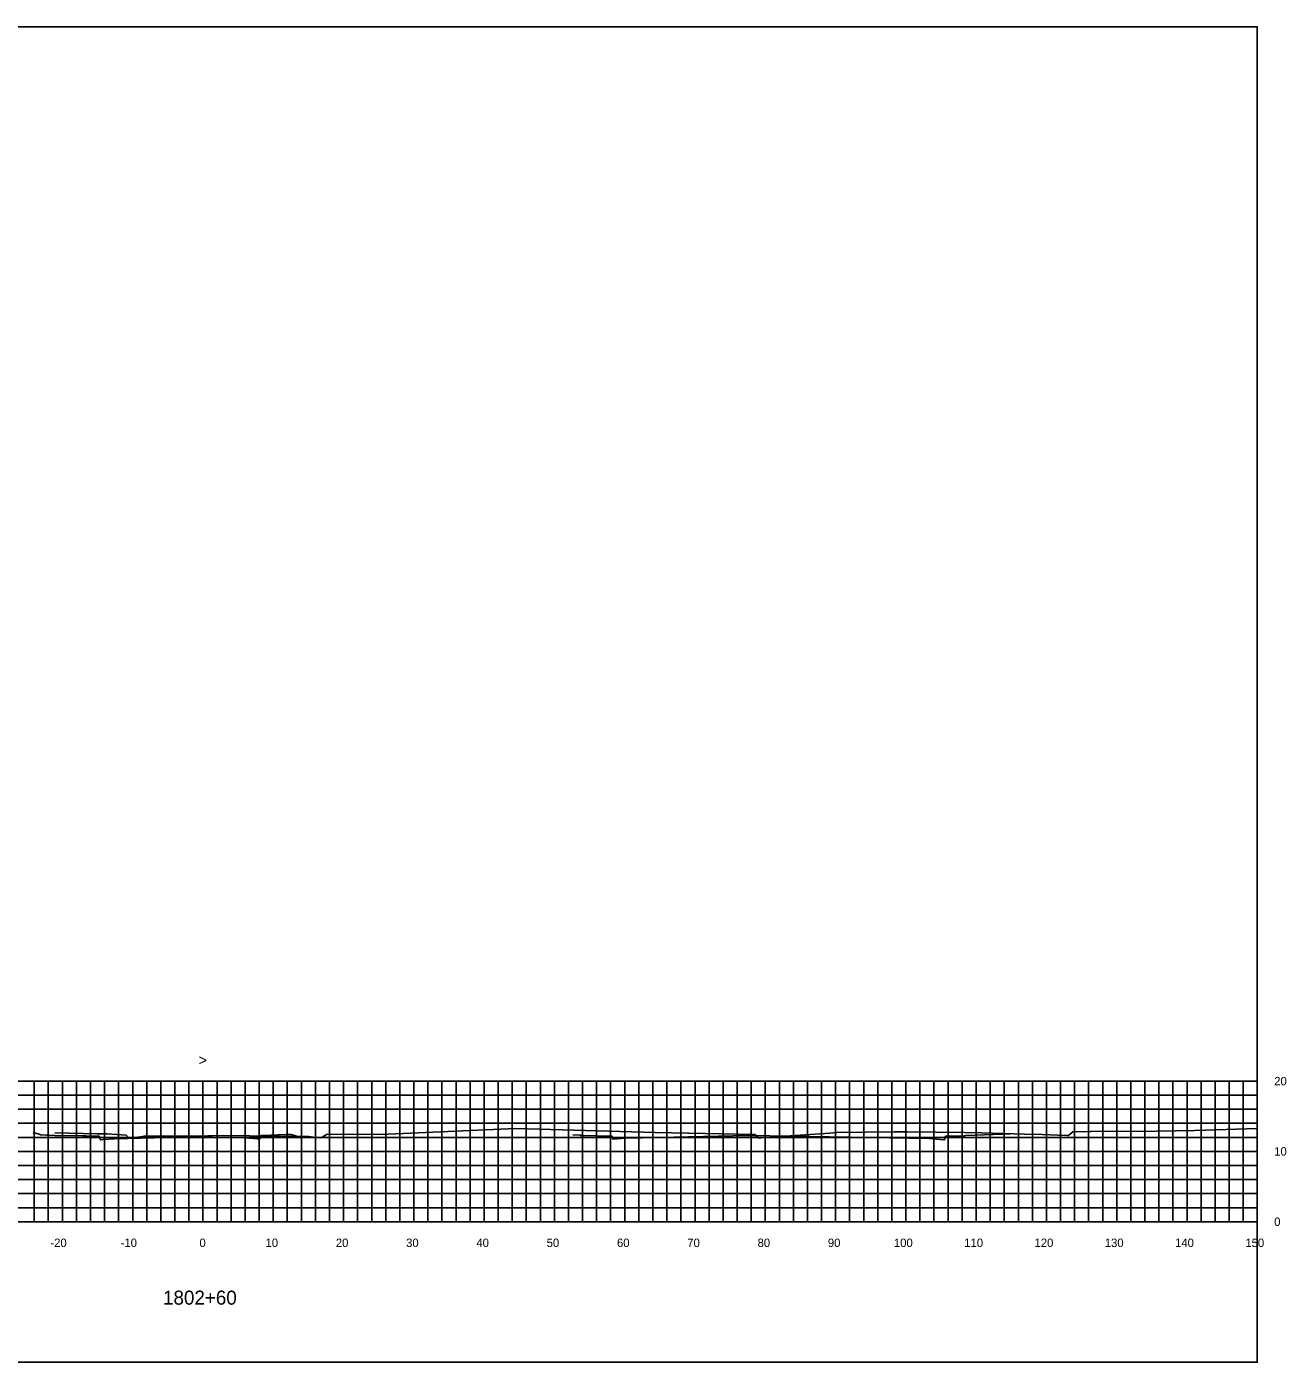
# Model space of a CAD drawing. Extents: x 1797759 to 1802785, y 249826 to 250371.
# Drawn here: x 1799971.1 to 1800150.3, y 249825.9 to 250015.9 of the extents above; entities that cross this region are included whole.
import ezdxf

# ---------------------------------------------------------------- set-up
doc = ezdxf.new("R2010")
doc.units = 0
for name, color, linetype in [('AXIS', 7, 'Continuous'), ('great seal', 7, 'Continuous'), ('Level 1', 7, 'Continuous'), ('Level 10', 7, 'Continuous'), ('Level 15', 7, 'Continuous'), ('Level 30', 7, 'Continuous'), ('Level 45', 7, 'Continuous'), ('Level 7', 7, 'Continuous')]:
    doc.layers.add(name, color=color, linetype=linetype)

msp = doc.modelspace()

# ---------------------------------------------------------------- linework, layer by layer
at = {"layer": 'AXIS'}
msp.add_lwpolyline([(1799846.22, 249825.85), (1800146.22, 249825.85), (1800146.22, 250015.85), (1799846.22, 250015.85)], close=True, dxfattribs=at)
msp.add_lwpolyline([(1800048.86, 249858.21), (1800049.85, 249858.18), (1800049.97, 249858.18), (1800050.01, 249858.07), (1800050.49, 249858.11), (1800053.95, 249858), (1800054.39, 249858), (1800054.54, 249857.6), (1800056.32, 249857.74), (1800061.11, 249857.85), (1800073.69, 249858.14), (1800076.85, 249858.08), (1800099.54, 249857.67), (1800101.61, 249857.51), (1800101.7, 249857.51), (1800101.71, 249857.53), (1800101.88, 249858.01), (1800101.9, 249858.01), (1800102.42, 249858.01), (1800104.5, 249858.09), (1800104.57, 249858.09), (1800104.74, 249858.1), (1800109.96, 249858.31), (1800111.02, 249858.35), (1800111.03, 249858.35), (1800111.06, 249858.36), (1800111.11, 249858.37)], dxfattribs=at)
at = {"layer": 'great seal'}
msp.add_lwpolyline([(1799975.14, 249858.51), (1799981.18, 249858.36), (1799982.19, 249858.37), (1799982.59, 249858.35), (1799985.31, 249858.16), (1799985.59, 249857.86), (1799985.72, 249857.74), (1799987.29, 249857.95), (1799987.87, 249858), (1799996.89, 249858.09), (1799999.09, 249858.13), (1800002.85, 249858.09), (1800011.3, 249857.97), (1800012.26, 249857.85), (1800013, 249857.78), (1800013.51, 249858.08), (1800013.8, 249858.27), (1800022.56, 249858.31), (1800033.19, 249858.78), (1800040.72, 249859.11), (1800060.56, 249858.56), (1800074.77, 249858.25), (1800075.1, 249857.9), (1800075.23, 249857.75), (1800075.7, 249857.8), (1800076.96, 249857.9), (1800085.42, 249858.45), (1800086.42, 249858.52), (1800094.57, 249858.63), (1800096.42, 249858.65), (1800104.54, 249858.55), (1800106.96, 249858.51), (1800113.08, 249858.32), (1800115.62, 249858.25), (1800117.82, 249858.18), (1800119.23, 249858.12), (1800119.36, 249858.11), (1800119.39, 249858.15), (1800119.96, 249858.64), (1800122.48, 249858.67), (1800131.83, 249858.71), (1800137.35, 249858.83), (1800146.22, 249859.1)], dxfattribs=at)
at = {"layer": 'Level 1'}
msp.add_lwpolyline([(1799972.07, 249858.56), (1799972.76, 249858.33), (1799973.15, 249858.2), (1799973.95, 249858.16), (1799974.15, 249858.16), (1799975.14, 249858.14), (1799979.14, 249858.08), (1799979.54, 249858.07), (1799981.14, 249858), (1799981.4, 249858), (1799981.47, 249858), (1799981.5, 249857.9), (1799981.63, 249857.5), (1799982.03, 249857.53), (1799983.63, 249857.66), (1799993.14, 249857.87), (1799995.61, 249857.93), (1799999.52, 249857.84), (1800002.31, 249857.78), (1800003.92, 249857.65), (1800004.3, 249857.62), (1800004.44, 249858.02), (1800004.47, 249858.12), (1800004.74, 249858.12), (1800004.8, 249858.12), (1800008.02, 249858.25), (1800008.79, 249858.28), (1800010, 249857.88), (1800010.3, 249857.98)], dxfattribs=at)
at = {"layer": 'Level 15'}
for p, q in [((1799846.22, 249865.85), (1800146.22, 249865.85)), ((1799972.22, 249845.85), (1799972.22, 249865.85)), ((1799974.22, 249845.85), (1799974.22, 249865.85)), ((1799976.22, 249845.85), (1799976.22, 249865.85)), ((1799978.22, 249845.85), (1799978.22, 249865.85)), ((1799980.22, 249845.85), (1799980.22, 249865.85)), ((1799982.22, 249845.85), (1799982.22, 249865.85)), ((1799984.22, 249845.85), (1799984.22, 249865.85)), ((1799986.22, 249845.85), (1799986.22, 249865.85)), ((1799988.22, 249845.85), (1799988.22, 249865.85)), ((1799990.22, 249845.85), (1799990.22, 249865.85)), ((1799992.22, 249845.85), (1799992.22, 249865.85)), ((1799994.22, 249845.85), (1799994.22, 249865.85)), ((1799996.22, 249845.85), (1799996.22, 249865.85)), ((1799998.22, 249845.85), (1799998.22, 249865.85)), ((1800000.22, 249845.85), (1800000.22, 249865.85)), ((1800002.22, 249845.85), (1800002.22, 249865.85)), ((1800004.22, 249845.85), (1800004.22, 249865.85)), ((1800006.22, 249845.85), (1800006.22, 249865.85)), ((1800008.22, 249845.85), (1800008.22, 249865.85)), ((1800010.22, 249845.85), (1800010.22, 249865.85)), ((1800012.22, 249845.85), (1800012.22, 249865.85)), ((1800014.22, 249845.85), (1800014.22, 249865.85)), ((1800016.22, 249845.85), (1800016.22, 249865.85)), ((1800018.22, 249845.85), (1800018.22, 249865.85)), ((1800020.22, 249845.85), (1800020.22, 249865.85)), ((1800022.22, 249845.85), (1800022.22, 249865.85)), ((1800024.22, 249845.85), (1800024.22, 249865.85)), ((1800026.22, 249845.85), (1800026.22, 249865.85)), ((1800028.22, 249845.85), (1800028.22, 249865.85)), ((1800030.22, 249845.85), (1800030.22, 249865.85)), ((1800032.22, 249845.85), (1800032.22, 249865.85)), ((1800034.22, 249845.85), (1800034.22, 249865.85)), ((1800036.22, 249845.85), (1800036.22, 249865.85)), ((1800038.22, 249845.85), (1800038.22, 249865.85)), ((1800040.22, 249845.85), (1800040.22, 249865.85)), ((1800042.22, 249845.85), (1800042.22, 249865.85)), ((1800044.22, 249845.85), (1800044.22, 249865.85)), ((1800046.22, 249845.85), (1800046.22, 249865.85)), ((1800048.22, 249845.85), (1800048.22, 249865.85)), ((1800050.22, 249845.85), (1800050.22, 249865.85)), ((1800052.22, 249845.85), (1800052.22, 249865.85)), ((1800054.22, 249845.85), (1800054.22, 249865.85)), ((1800056.22, 249845.85), (1800056.22, 249865.85)), ((1800058.22, 249845.85), (1800058.22, 249865.85)), ((1800060.22, 249845.85), (1800060.22, 249865.85)), ((1800062.22, 249845.85), (1800062.22, 249865.85)), ((1800064.22, 249845.85), (1800064.22, 249865.85)), ((1800066.22, 249845.85), (1800066.22, 249865.85)), ((1800068.22, 249845.85), (1800068.22, 249865.85)), ((1800070.22, 249845.85), (1800070.22, 249865.85)), ((1800072.22, 249845.85), (1800072.22, 249865.85)), ((1800074.22, 249845.85), (1800074.22, 249865.85)), ((1800076.22, 249845.85), (1800076.22, 249865.85)), ((1800078.22, 249845.85), (1800078.22, 249865.85)), ((1800080.22, 249845.85), (1800080.22, 249865.85)), ((1800082.22, 249845.85), (1800082.22, 249865.85)), ((1800084.22, 249845.85), (1800084.22, 249865.85)), ((1800086.22, 249845.85), (1800086.22, 249865.85)), ((1800088.22, 249845.85), (1800088.22, 249865.85)), ((1800090.22, 249845.85), (1800090.22, 249865.85)), ((1800092.22, 249845.85), (1800092.22, 249865.85)), ((1800094.22, 249845.85), (1800094.22, 249865.85)), ((1800096.22, 249845.85), (1800096.22, 249865.85)), ((1800098.22, 249845.85), (1800098.22, 249865.85)), ((1800100.22, 249845.85), (1800100.22, 249865.85)), ((1800102.22, 249845.85), (1800102.22, 249865.85)), ((1800104.22, 249845.85), (1800104.22, 249865.85)), ((1800106.22, 249845.85), (1800106.22, 249865.85)), ((1800108.22, 249845.85), (1800108.22, 249865.85)), ((1800110.22, 249845.85), (1800110.22, 249865.85)), ((1800112.22, 249845.85), (1800112.22, 249865.85)), ((1800114.22, 249845.85), (1800114.22, 249865.85)), ((1800116.22, 249845.85), (1800116.22, 249865.85)), ((1800118.22, 249845.85), (1800118.22, 249865.85)), ((1800120.22, 249845.85), (1800120.22, 249865.85)), ((1800122.22, 249845.85), (1800122.22, 249865.85)), ((1800124.22, 249845.85), (1800124.22, 249865.85)), ((1800126.22, 249845.85), (1800126.22, 249865.85)), ((1800128.22, 249845.85), (1800128.22, 249865.85)), ((1800130.22, 249845.85), (1800130.22, 249865.85)), ((1800132.22, 249845.85), (1800132.22, 249865.85)), ((1800134.22, 249845.85), (1800134.22, 249865.85)), ((1800136.22, 249845.85), (1800136.22, 249865.85)), ((1800138.22, 249845.85), (1800138.22, 249865.85)), ((1800140.22, 249845.85), (1800140.22, 249865.85)), ((1800142.22, 249845.85), (1800142.22, 249865.85)), ((1800144.22, 249845.85), (1800144.22, 249865.85)), ((1800146.22, 249845.85), (1800146.22, 249865.85)), ((1799846.22, 249863.85), (1800146.22, 249863.85)), ((1799846.22, 249861.85), (1800146.22, 249861.85)), ((1799846.22, 249859.85), (1800146.22, 249859.85)), ((1799846.22, 249857.85), (1800146.22, 249857.85)), ((1799846.22, 249855.85), (1800146.22, 249855.85)), ((1799846.22, 249853.85), (1800146.22, 249853.85)), ((1799846.22, 249851.85), (1800146.22, 249851.85)), ((1799846.22, 249849.85), (1800146.22, 249849.85)), ((1799846.22, 249847.85), (1800146.22, 249847.85)), ((1799846.22, 249845.85), (1800146.22, 249845.85))]:
    msp.add_line(p, q, dxfattribs=at)
at = {"layer": 'Level 30'}
for p, q in [((1800146.22, 249845.85), (1800146.22, 249865.85)), ((1800146.28, 249865.85), (1800146.22, 249865.85)), ((1800146.28, 249855.85), (1800146.22, 249855.85)), ((1799846.22, 249845.85), (1800146.22, 249845.85)), ((1799976.22, 249845.79), (1799976.22, 249845.85)), ((1799986.22, 249845.79), (1799986.22, 249845.85)), ((1799996.22, 249845.79), (1799996.22, 249845.85)), ((1800006.22, 249845.79), (1800006.22, 249845.85)), ((1800016.22, 249845.79), (1800016.22, 249845.85)), ((1800026.22, 249845.79), (1800026.22, 249845.85)), ((1800036.22, 249845.79), (1800036.22, 249845.85)), ((1800046.22, 249845.79), (1800046.22, 249845.85)), ((1800056.22, 249845.79), (1800056.22, 249845.85)), ((1800066.22, 249845.79), (1800066.22, 249845.85)), ((1800076.22, 249845.79), (1800076.22, 249845.85)), ((1800086.22, 249845.79), (1800086.22, 249845.85)), ((1800096.22, 249845.79), (1800096.22, 249845.85)), ((1800106.22, 249845.79), (1800106.22, 249845.85)), ((1800116.22, 249845.79), (1800116.22, 249845.85)), ((1800126.22, 249845.79), (1800126.22, 249845.85)), ((1800136.22, 249845.79), (1800136.22, 249845.85)), ((1800146.22, 249845.79), (1800146.22, 249845.85)), ((1800146.28, 249845.85), (1800146.22, 249845.85))]:
    msp.add_line(p, q, dxfattribs=at)

# ---------------------------------------------------------------- texts
at = {"layer": 'Level 10'}
msp.add_text('1802+60', height=2, dxfattribs=at).set_placement((1799990.54, 249834.05))
at = {"layer": 'Level 30'}
msp.add_text('>', height=1.5, dxfattribs=at).set_placement((1799995.61, 249868.1))
at = {"layer": 'Level 45'}
for s, p in [('-20', (1799974.51, 249842.25)), ('-10', (1799984.51, 249842.25)), ('0', (1799995.72, 249842.25)), ('10', (1800005.12, 249842.25)), ('20', (1800015.12, 249842.25)), ('30', (1800025.12, 249842.25)), ('40', (1800035.12, 249842.25)), ('50', (1800045.12, 249842.25)), ('60', (1800055.12, 249842.25)), ('70', (1800065.12, 249842.25)), ('80', (1800075.12, 249842.25)), ('90', (1800085.12, 249842.25)), ('100', (1800094.52, 249842.25)), ('110', (1800104.52, 249842.25)), ('120', (1800114.52, 249842.25)), ('130', (1800124.52, 249842.25)), ('140', (1800134.52, 249842.25)), ('150', (1800144.52, 249842.25))]:
    msp.add_text(s, height=1.2, dxfattribs=at).set_placement(p)
at = {"layer": 'Level 7'}
for s, p in [('20', (1800148.62, 249865.25)), ('10', (1800148.62, 249855.25)), ('0', (1800148.62, 249845.25))]:
    msp.add_text(s, height=1.2, dxfattribs=at).set_placement(p)

doc.saveas('drawing.dxf')
